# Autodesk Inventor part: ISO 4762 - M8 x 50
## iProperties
Comments: To add or edit properties for Autodesk Inventor files, use iProperties.
Created: 2004-03
Part Number: ISO 4762 - M8 x 50
Vendor: Autodesk Inc.
Document SubType Name: Modeling
Designer: rak
Material: Default
Description: Hexagon Socket Head Cap Screw
Standard: ISO 4762
Size Designation: M8 x 50
Alert: To add or edit properties for Autodesk Inventor files, use iProperties.
Control State: 0
Master: False
Checked Out: False
Shininess: 64.0
Length Units: 11269
Angle Units: 11279
Time Units: 11290
Mass Units: 11283
Length Display Precision: 3
Angle Display Precision: 2
Compacted: True
EGR: 1
Density: 0.0
Volumn: 0.0
Area: 0.0
PropertySet Name: Model Information
Author: rak
Revision Number: 8
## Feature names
1. Body [Revolution]
2. Slot [Extrusion]
3. Fillet1
4. Chamfer1
